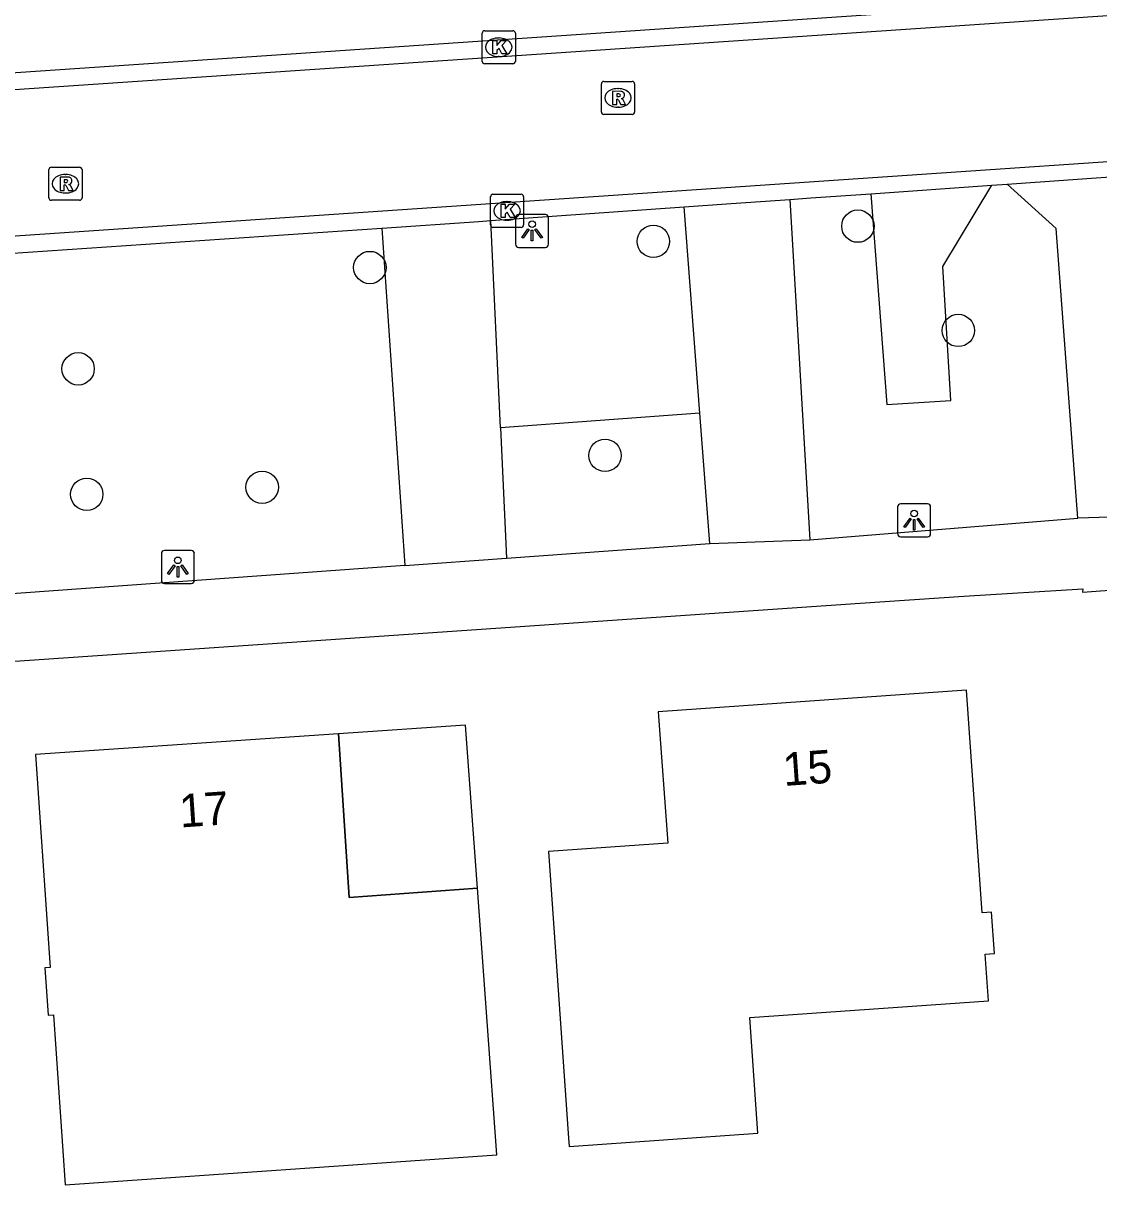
# Model space of a CAD drawing. Extents: x 162675 to 163482, y 379761 to 381227.
# Drawn here: x 162974.72 to 163007.21, y 380317.63 to 380352.72 of the extents above; entities that cross this region are included whole.
import ezdxf

# ---------------------------------------------------------------- set-up
doc = ezdxf.new("R2010")
doc.units = 0
for name, color, linetype in [('IMGEO_Berm_halfverhard', 7, 'Continuous'), ('IMGEO_Boom', 7, 'Continuous'), ('IMGEO_Kolk', 7, 'Continuous'), ('IMGEO_Lichtpunt', 7, 'Continuous'), ('IMGEO_Pand', 7, 'Continuous'), ('IMGEO_Pand_nummerreeks', 7, 'Continuous'), ('IMGEO_Pand_overbouw', 7, 'Continuous'), ('IMGEO_Rijbaan_lokaal_gesloten', 7, 'Continuous'), ('IMGEO_Rijbaan_lokaal_open', 7, 'Continuous'), ('IMGEO_Rioolput', 7, 'Continuous'), ('IMGEO_Voetpad_open', 7, 'Continuous')]:
    doc.layers.add(name, color=color, linetype=linetype)

msp = doc.modelspace()

# ---------------------------------------------------------------- linework, layer by layer
at = {"layer": 'IMGEO_Berm_halfverhard'}
for points in [[(163000.331, 380347.571), (163000.815, 380341.201), (163002.74, 380341.322), (163002.497, 380345.371), (163003.983, 380347.829)], [(162995.163, 380340.945), (162989.136, 380340.5)]]:
    msp.add_lwpolyline(points, dxfattribs=at)
at = {"layer": 'IMGEO_Boom'}
for centre in [(162999.936, 380346.59), (162993.758, 380346.129), (162985.192, 380345.34), (163002.968, 380343.439), (162976.38, 380342.28), (162992.297, 380339.664), (162976.641, 380338.489), (162981.939, 380338.702)]:
    msp.add_circle(centre, 0.489, dxfattribs=at)
at = {"layer": 'IMGEO_Kolk'}
for p, q in [((162988.587, 380351.568), (162988.587, 380352.42)), ((162988.662, 380352.494), (162989.514, 380352.494)), ((162989.588, 380352.42), (162989.588, 380351.568)), ((162989.075, 380352.274), (162989.1, 380352.274)), ((162989.098, 380351.714), (162989.073, 380351.714)), ((162989.514, 380351.494), (162988.662, 380351.494)), ((162988.837, 380346.625), (162988.837, 380347.477)), ((162988.912, 380347.551), (162989.764, 380347.551)), ((162989.838, 380347.477), (162989.838, 380346.625)), ((162989.325, 380347.331), (162989.35, 380347.331)), ((162989.348, 380346.771), (162989.323, 380346.771)), ((162989.764, 380346.551), (162988.912, 380346.551))]:
    msp.add_line(p, q, dxfattribs=at)
for points in [[(162988.587, 380351.568), (162988.587, 380352.42)], [(162988.662, 380352.494), (162989.514, 380352.494)], [(162989.588, 380352.42), (162989.588, 380351.568)], [(162988.908, 380352.194), (162989.031, 380352.194), (162989.031, 380352.043), (162989.161, 380352.194), (162989.325, 380352.194), (162989.179, 380352.043), (162989.332, 380351.794), (162989.18, 380351.794), (162989.095, 380351.958), (162989.031, 380351.891), (162989.031, 380351.794), (162988.908, 380351.794), (162988.908, 380352.194)], [(162989.514, 380351.494), (162988.662, 380351.494)], [(162988.837, 380346.625), (162988.837, 380347.477)], [(162988.912, 380347.551), (162989.764, 380347.551)], [(162989.838, 380347.477), (162989.838, 380346.625)], [(162989.158, 380347.251), (162989.281, 380347.251), (162989.281, 380347.1), (162989.411, 380347.251), (162989.575, 380347.251), (162989.429, 380347.1), (162989.582, 380346.851), (162989.43, 380346.851), (162989.345, 380347.015), (162989.281, 380346.948), (162989.281, 380346.851), (162989.158, 380346.851), (162989.158, 380347.251)], [(162989.764, 380346.551), (162988.912, 380346.551)]]:
    msp.add_lwpolyline(points, dxfattribs=at)
for centre, start, end in [((162988.664, 380352.418), 91.552, 178.448), ((162988.664, 380352.418), 91.552, 178.448), ((162989.512, 380352.418), 1.552, 88.448), ((162989.512, 380352.418), 1.552, 88.448), ((162988.664, 380351.57), 181.552, 268.448), ((162988.664, 380351.57), 181.552, 268.448), ((162989.512, 380351.57), 271.552, 358.448), ((162989.512, 380351.57), 271.552, 358.448), ((162988.914, 380347.475), 91.552, 178.448), ((162988.914, 380347.475), 91.552, 178.448), ((162989.762, 380347.475), 1.552, 88.448), ((162989.762, 380347.475), 1.552, 88.448), ((162988.914, 380346.627), 181.552, 268.448), ((162988.914, 380346.627), 181.552, 268.448), ((162989.762, 380346.627), 271.552, 358.448), ((162989.762, 380346.627), 271.552, 358.448)]:
    msp.add_arc(centre, 0.0765, start, end, dxfattribs=at)
for centre, major_axis, ratio, start_param, end_param in [((162989.074, 380351.994), (-0.387, 0.002), 0.722429, 4.712389, 7.853982), ((162989.099, 380351.994), (-0.39, 0.002), 0.717154, 1.570796, 4.712389), ((162989.324, 380347.051), (-0.387, 0.002), 0.722429, 4.712389, 7.853982), ((162989.349, 380347.051), (-0.39, 0.002), 0.717154, 1.570796, 4.712389)]:
    msp.add_ellipse(centre, major_axis=major_axis, ratio=ratio, start_param=start_param, end_param=end_param, dxfattribs=at)
at = {"layer": 'IMGEO_Lichtpunt'}
for p, q in [((162989.594, 380346.849), (162989.594, 380346.042)), ((162989.594, 380346.849), (162989.594, 380346.042)), ((162990.496, 380346.944), (162989.688, 380346.944)), ((162990.496, 380346.944), (162989.688, 380346.944)), ((162990.59, 380346.042), (162990.59, 380346.849)), ((162990.59, 380346.042), (162990.59, 380346.849)), ((162989.688, 380345.948), (162990.496, 380345.948)), ((162989.688, 380345.948), (162990.496, 380345.948)), ((163001.137, 380338.109), (163001.137, 380337.302)), ((163001.137, 380338.109), (163001.137, 380337.302)), ((163002.039, 380338.204), (163001.231, 380338.204)), ((163002.039, 380338.204), (163001.231, 380338.204)), ((163002.133, 380337.302), (163002.133, 380338.109)), ((163002.133, 380337.302), (163002.133, 380338.109)), ((163001.231, 380337.208), (163002.039, 380337.208)), ((163001.231, 380337.208), (163002.039, 380337.208)), ((162978.894, 380336.696), (162978.894, 380335.889)), ((162978.894, 380336.696), (162978.894, 380335.889)), ((162979.796, 380336.791), (162978.988, 380336.791)), ((162979.796, 380336.791), (162978.988, 380336.791)), ((162979.89, 380335.889), (162979.89, 380336.696)), ((162979.89, 380335.889), (162979.89, 380336.696)), ((162978.988, 380335.795), (162979.796, 380335.795)), ((162978.988, 380335.795), (162979.796, 380335.795))]:
    msp.add_line(p, q, dxfattribs=at)
for points in [[(162989.968, 380346.513), (162990.007, 380346.485), (162989.819, 380346.223), (162989.781, 380346.25), (162989.968, 380346.513)], [(162990.07, 380346.465), (162990.117, 380346.465), (162990.117, 380346.143), (162990.07, 380346.143), (162990.07, 380346.465)], [(162990.18, 380346.485), (162990.218, 380346.512), (162990.405, 380346.25), (162990.366, 380346.222), (162990.18, 380346.485)], [(163001.511, 380337.773), (163001.55, 380337.745), (163001.362, 380337.483), (163001.324, 380337.51), (163001.511, 380337.773)], [(163001.613, 380337.725), (163001.66, 380337.725), (163001.66, 380337.403), (163001.613, 380337.403), (163001.613, 380337.725)], [(163001.723, 380337.745), (163001.761, 380337.772), (163001.948, 380337.51), (163001.909, 380337.482), (163001.723, 380337.745)], [(162979.268, 380336.36), (162979.307, 380336.332), (162979.119, 380336.07), (162979.081, 380336.097), (162979.268, 380336.36)], [(162979.37, 380336.312), (162979.417, 380336.312), (162979.417, 380335.99), (162979.37, 380335.99), (162979.37, 380336.312)], [(162979.48, 380336.332), (162979.518, 380336.359), (162979.705, 380336.097), (162979.666, 380336.069), (162979.48, 380336.332)]]:
    msp.add_lwpolyline(points, dxfattribs=at)
for centre in [(162990.093, 380346.647), (163001.636, 380337.907), (162979.393, 380336.494)]:
    msp.add_circle(centre, 0.0994, dxfattribs=at)
for centre, start, end in [((162989.688, 380346.849), 90, 180), ((162989.688, 380346.849), 90, 180), ((162990.496, 380346.849), 0, 90), ((162990.496, 380346.849), 0, 90), ((162989.688, 380346.042), 180, 270), ((162989.688, 380346.042), 180, 270), ((162990.496, 380346.042), 270, 0), ((162990.496, 380346.042), 270, 360), ((163001.231, 380338.109), 90, 180), ((163001.231, 380338.109), 90, 180), ((163002.039, 380338.109), 0, 90), ((163002.039, 380338.109), 0, 90), ((163001.231, 380337.302), 180, 270), ((163001.231, 380337.302), 180, 270), ((163002.039, 380337.302), 270, 0), ((163002.039, 380337.302), 270, 360), ((162978.988, 380336.696), 90, 180), ((162978.988, 380336.696), 90, 180), ((162979.796, 380336.696), 0, 90), ((162979.796, 380336.696), 0, 90), ((162978.988, 380335.889), 180, 270), ((162978.988, 380335.889), 180, 270), ((162979.796, 380335.889), 270, 0), ((162979.796, 380335.889), 270, 360)]:
    msp.add_arc(centre, 0.0946, start, end, dxfattribs=at)
at = {"layer": 'IMGEO_Pand'}
for points in [[(163003.213, 380332.575), (162993.902, 380331.914), (162994.19, 380327.954), (162990.593, 380327.695), (162991.195, 380319.04), (162991.212, 380318.791), (162996.918, 380319.188), (162996.675, 380322.688), (163003.88, 380323.189), (163003.779, 380324.6), (163004.059, 380324.62), (163003.97, 380325.867), (163003.691, 380325.847), (163003.213, 380332.575)], [(162988.442, 380326.588), (162984.571, 380326.305), (162984.244, 380331.256), (162975.096, 380330.63), (162975.536, 380324.197), (162975.376, 380324.186), (162975.474, 380322.753), (162975.634, 380322.763), (162975.985, 380317.631), (162989.031, 380318.534), (162988.442, 380326.588)]]:
    msp.add_lwpolyline(points, dxfattribs=at)
at = {"layer": 'IMGEO_Pand_overbouw'}
msp.add_lwpolyline([(162988.442, 380326.588), (162988.081, 380331.519), (162984.244, 380331.256), (162984.571, 380326.305)], close=True, dxfattribs=at)
at = {"layer": 'IMGEO_Rijbaan_lokaal_gesloten'}
for points in [[(163129.435, 380356.95), (163028.95, 380349.989), (162935.401, 380343.628)], [(162940.821, 380348.438), (163054.493, 380356.141)]]:
    msp.add_lwpolyline(points, dxfattribs=at)
at = {"layer": 'IMGEO_Rijbaan_lokaal_open'}
for points in [[(163006.568, 380353.401), (162940.787, 380348.935)], [(163004.444, 380347.862), (163010.118, 380348.264)], [(163000.331, 380347.571), (163003.983, 380347.829)], [(163003.983, 380347.829), (163004.444, 380347.862)], [(162994.692, 380347.172), (162996.104, 380347.272), (162997.878, 380347.397)], [(162997.878, 380347.397), (162998.511, 380347.442), (163000.331, 380347.571)], [(162988.843, 380346.757), (162994.692, 380347.172)], [(162985.556, 380346.533), (162988.485, 380346.732), (162988.843, 380346.757)], [(162960.595, 380344.836), (162985.556, 380346.533)]]:
    msp.add_lwpolyline(points, dxfattribs=at)
at = {"layer": 'IMGEO_Rioolput'}
for p, q in [((162992.188, 380350.038), (162992.188, 380350.89)), ((162992.263, 380350.964), (162993.115, 380350.964)), ((162993.189, 380350.89), (162993.189, 380350.038)), ((162992.676, 380350.744), (162992.701, 380350.744)), ((162992.699, 380350.184), (162992.674, 380350.184)), ((162993.115, 380349.964), (162992.263, 380349.964)), ((162975.496, 380347.445), (162975.496, 380348.297)), ((162975.571, 380348.371), (162976.423, 380348.371)), ((162975.984, 380348.151), (162976.009, 380348.151)), ((162976.497, 380348.297), (162976.497, 380347.445)), ((162976.423, 380347.371), (162975.571, 380347.371)), ((162976.007, 380347.591), (162975.982, 380347.591))]:
    msp.add_line(p, q, dxfattribs=at)
for points in [[(162992.188, 380350.038), (162992.188, 380350.89)], [(162992.263, 380350.964), (162993.115, 380350.964)], [(162993.189, 380350.89), (162993.189, 380350.038)], [(162992.777, 380350.662), (162992.525, 380350.664), (162992.525, 380350.264)], [(162992.703, 380350.583), (162992.649, 380350.583), (162992.649, 380350.502)], [(162992.525, 380350.264), (162992.649, 380350.264), (162992.649, 380350.426), (162992.66, 380350.426)], [(162992.649, 380350.502), (162992.701, 380350.502)], [(162992.707, 380350.397), (162992.778, 380350.264), (162992.918, 380350.264), (162992.853, 380350.39)], [(162993.115, 380349.964), (162992.263, 380349.964)], [(162975.496, 380347.445), (162975.496, 380348.297)], [(162975.571, 380348.371), (162976.423, 380348.371)], [(162976.085, 380348.069), (162975.833, 380348.071), (162975.833, 380347.671)], [(162976.497, 380348.297), (162976.497, 380347.445)], [(162975.833, 380347.671), (162975.957, 380347.671), (162975.957, 380347.833), (162975.968, 380347.833)], [(162976.011, 380347.99), (162975.957, 380347.99), (162975.957, 380347.909)], [(162975.957, 380347.909), (162976.009, 380347.909)], [(162976.015, 380347.804), (162976.086, 380347.671), (162976.226, 380347.671), (162976.161, 380347.797)], [(162976.423, 380347.371), (162975.571, 380347.371)]]:
    msp.add_lwpolyline(points, dxfattribs=at)
for centre, radius, start, end in [((162992.265, 380350.888), 0.0765, 91.552, 178.448), ((162992.265, 380350.888), 0.0765, 91.552, 178.448), ((162993.113, 380350.888), 0.0765, 1.552, 88.448), ((162993.113, 380350.888), 0.0765, 1.552, 88.448), ((162992.709, 380350.487), 0.0964, 77.0061, 93.1865), ((162992.723, 380350.544), 0.0378, 276.6634, 79.6772), ((162992.776, 380350.552), 0.109, 350.3612, 89.416), ((162992.774, 380350.552), 0.112, 277.5842, 350.9817), ((162992.659, 380350.373), 0.0533, 26.0293, 88.6989), ((162992.685, 380350.691), 0.19, 274.7715, 282.9687), ((162992.758, 380350.337), 0.108, 29.5134, 73.7905), ((162992.265, 380350.04), 0.0765, 181.552, 268.448), ((162992.265, 380350.04), 0.0765, 181.552, 268.448), ((162993.113, 380350.04), 0.0765, 271.552, 358.448), ((162993.113, 380350.04), 0.0765, 271.552, 358.448), ((162975.573, 380348.295), 0.0765, 91.552, 178.448), ((162975.573, 380348.295), 0.0765, 91.552, 178.448), ((162976.084, 380347.959), 0.109, 350.3612, 89.416), ((162976.421, 380348.295), 0.0765, 1.552, 88.448), ((162976.421, 380348.295), 0.0765, 1.552, 88.448), ((162975.967, 380347.78), 0.0533, 26.0293, 88.6989), ((162975.993, 380348.098), 0.19, 274.7715, 282.9687), ((162976.017, 380347.894), 0.0964, 77.0061, 93.1865), ((162976.031, 380347.951), 0.0378, 276.6634, 79.6772), ((162976.082, 380347.959), 0.112, 277.5842, 350.9817), ((162976.066, 380347.744), 0.108, 29.5134, 73.7905), ((162975.573, 380347.447), 0.0765, 181.552, 268.448), ((162975.573, 380347.447), 0.0765, 181.552, 268.448), ((162976.421, 380347.447), 0.0765, 271.552, 358.448), ((162976.421, 380347.447), 0.0765, 271.552, 358.448)]:
    msp.add_arc(centre, radius, start, end, dxfattribs=at)
for centre, major_axis, ratio, start_param, end_param in [((162992.675, 380350.464), (-0.387, 0.002), 0.722429, 4.712389, 7.853982), ((162992.7, 380350.464), (-0.39, 0.002), 0.717154, 1.570796, 4.712389), ((162975.983, 380347.871), (-0.387, 0.002), 0.722429, 4.712389, 7.853982), ((162976.008, 380347.871), (-0.39, 0.002), 0.717154, 1.570796, 4.712389)]:
    msp.add_ellipse(centre, major_axis=major_axis, ratio=ratio, start_param=start_param, end_param=end_param, dxfattribs=at)
at = {"layer": 'IMGEO_Voetpad_open'}
for points in [[(163006.583, 380337.77), (163005.924, 380346.518), (163004.444, 380347.862)], [(162997.878, 380347.397), (162998.488, 380337.109)], [(162995.163, 380340.945), (162994.692, 380347.172)], [(162989.136, 380340.5), (162988.843, 380346.757)], [(162985.556, 380346.533), (162986.249, 380336.337)], [(162995.461, 380336.998), (162995.163, 380340.945)], [(162989.136, 380340.5), (162989.321, 380336.558)], [(162998.488, 380337.109), (163006.583, 380337.77)], [(163009.464, 380337.857), (163006.583, 380337.77)], [(162936.743, 380330.858), (163000, 380335.199), (163003.141, 380335.415), (163006.73, 380335.638), (163006.725, 380335.529), (163009.593, 380335.742), (163009.587, 380336.032), (163024.481, 380337.057)], [(162989.321, 380336.558), (162995.461, 380336.998)], [(162995.461, 380336.998), (162998.488, 380337.109)], [(162986.249, 380336.337), (162989.321, 380336.558)], [(162986.249, 380336.337), (162973.534, 380335.425), (162960.085, 380334.522)]]:
    msp.add_lwpolyline(points, dxfattribs=at)

# ---------------------------------------------------------------- texts
at = {"layer": 'IMGEO_Pand_nummerreeks'}
for s, rotation, p in [('15', 4.0623, (162997.702, 380329.677)), ('17', 3.9133, (162979.471, 380328.423))]:
    msp.add_text(s, height=1, rotation=rotation, dxfattribs=at).set_placement(p)

doc.saveas('drawing.dxf')
